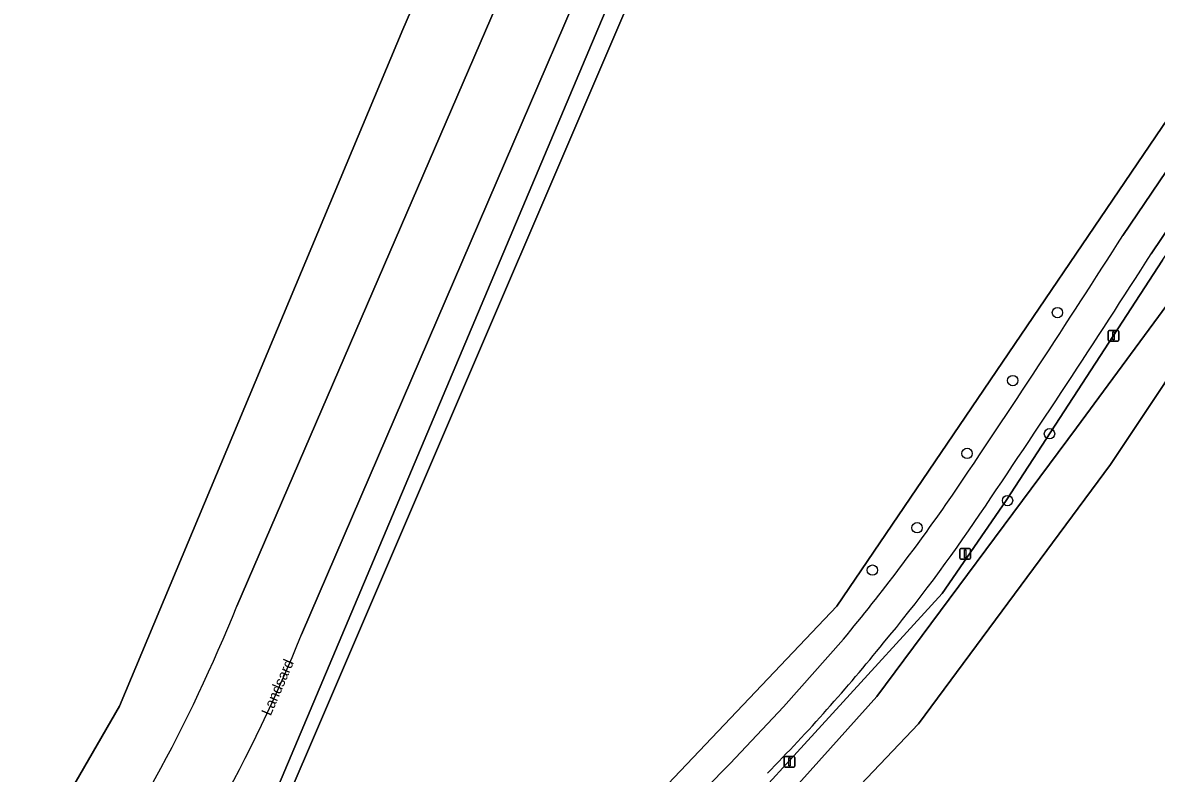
# Model space of a CAD drawing. Extents: x 155209 to 156748, y 385356 to 388487.
# Drawn here: x 155855.7 to 155962.6, y 385866.9 to 385937.7 of the extents above; entities that cross this region are included whole.
import ezdxf

# ---------------------------------------------------------------- set-up
doc = ezdxf.new("R2010")
doc.units = 0
for name, color, linetype in [('IMGEO_Berm_groen', 7, 'Continuous'), ('IMGEO_Boom', 7, 'Continuous'), ('IMGEO_Fietspad_gesloten', 7, 'Continuous'), ('IMGEO_Gemengd_bos', 7, 'Continuous'), ('IMGEO_Groenvoorziening', 7, 'Continuous'), ('IMGEO_Lichtmast', 7, 'Continuous'), ('IMGEO_Meer_plas_ven_vijver', 7, 'Continuous'), ('IMGEO_Naaldbos', 7, 'Continuous'), ('IMGEO_Oever', 7, 'Continuous'), ('IMGEO_Openbare_ruimte_label', 7, 'Continuous'), ('IMGEO_Rijbaan_lokaal_gesloten', 7, 'Continuous'), ('IMGEO_Waterloop', 7, 'Continuous')]:
    doc.layers.add(name, color=color, linetype=linetype)

msp = doc.modelspace()

# ---------------------------------------------------------------- linework, layer by layer
at = {"layer": 'IMGEO_Berm_groen'}
for points in [[(155908.98, 385959.23), (155905.66, 385960.64), (155915.24, 385982.82), (155916.17, 385982.42), (155916.98, 385984.34), (155917.62, 385985.86), (155917.92, 385986.55), (155913.79, 385988.33), (155913.52, 385987.69), (155912.88, 385986.21), (155891.58, 385937.04), (155864.83, 385873.2), (155853.13, 385852.94), (155810.49, 385814.26), (155804.37, 385808.7), (155774.12, 385781.08), (155771.15, 385778.38), (155769.03, 385773.41), (155767.97, 385771.34), (155768.61, 385770.6), (155770.85, 385768.09), (155773.86, 385770.85), (155810.94, 385803.67), (155837.84, 385827.57)], [(155875.91, 385882.64), (155908.98, 385959.23)], [(155959.49, 385917.6), (155967.71, 385929.79), (155976.74, 385943.04), (155976.86, 385943.15), (155976.15, 385944.26), (155974.75, 385944.88), (155932.5, 385882.64), (155851.64, 385797.46), (155851.5, 385797.12)], [(155921.77, 385861.19), (155942.45, 385883.84), (155948.49, 385892.6), (155963.23, 385915.28), (155979.15, 385938.71), (155979.16, 385939.55), (155978.86, 385940.02), (155970.6, 385928.4), (155962.17, 385915.88)], [(155887.11, 385831.96), (155922.46, 385867.78), (155927.49, 385873.15), (155933.14, 385879.54)]]:
    msp.add_lwpolyline(points, dxfattribs=at)
for centre, radius, start, end in [((155057.31, 386492.1), 1069.56, 325.94143, 327.51135), ((155056.98, 386494.04), 1074.07, 325.8648, 327.43296), ((155776.14, 386009.1), 203.56, 320.4704, 325.2588), ((155816.96, 385978.33), 155.64, 320.4219, 326.0119), ((155732.32, 385940.67), 154.88, 324.673, 337.9939), ((155802.68, 385987.72), 172.63, 315.5693, 321.0394)]:
    msp.add_arc(centre, radius, start, end, dxfattribs=at)
at = {"layer": 'IMGEO_Boom'}
for centre in [(155953.32, 385910.33), (155949.1, 385903.92), (155952.57, 385898.91), (155944.79, 385897.05), (155948.61, 385892.6), (155940.08, 385890.04), (155935.86, 385886.04)]:
    msp.add_circle(centre, 0.489, dxfattribs=at)
at = {"layer": 'IMGEO_Fietspad_gesloten'}
for points in [[(155962.17, 385915.88), (155970.6, 385928.4), (155978.86, 385940.02), (155979.13, 385940.39), (155976.97, 385943.25), (155976.86, 385943.15), (155976.74, 385943.04), (155967.71, 385929.79), (155959.49, 385917.6)], [(155933.14, 385879.54), (155927.49, 385873.15), (155922.46, 385867.78), (155887.11, 385831.96)]]:
    msp.add_lwpolyline(points, dxfattribs=at)
for centre, radius, start, end in [((155057.31, 386492.1), 1069.56, 325.94143, 327.51135), ((155056.98, 386494.04), 1074.07, 325.8648, 327.43296), ((155776.14, 386009.1), 203.56, 320.4704, 325.2588), ((155816.96, 385978.33), 155.64, 320.4219, 326.0119), ((155802.68, 385987.72), 172.63, 315.5693, 321.0394)]:
    msp.add_arc(centre, radius, start, end, dxfattribs=at)
at = {"layer": 'IMGEO_Gemengd_bos'}
msp.add_lwpolyline([(155872.65, 386005.2), (155867.03, 385991.83), (155868.12, 385991.46), (155859.4, 385970.5), (155853.12, 385955.51), (155833.54, 385909.24), (155796.45, 385820.47), (155810.49, 385814.26), (155853.13, 385852.94), (155864.83, 385873.2), (155891.58, 385937.04), (155912.88, 385986.21)], dxfattribs=at)
at = {"layer": 'IMGEO_Groenvoorziening'}
for points in [[(155783.19, 385764.8), (155786.45, 385768.76), (155814.49, 385793.57), (155841.44, 385817.51), (155847.37, 385823.23), (155851.61, 385826.93), (155858.57, 385833.47), (155863.57, 385838.09), (155867.53, 385841.42), (155870.87, 385844.48), (155910.3, 385937.91), (155931.88, 385987.98), (155929.14, 385989.38), (155882.02, 385879.97)], [(155963.23, 385915.28), (155948.49, 385892.6), (155942.45, 385883.84), (155921.77, 385861.19), (155901.12, 385837.98), (155877.21, 385813.21), (155877.16, 385813.41), (155877.27, 385813.85), (155877.54, 385814.49), (155878.1, 385815.73), (155878.45, 385816.54), (155878.76, 385817.29), (155879.14, 385818.21)]]:
    msp.add_lwpolyline(points, dxfattribs=at)
msp.add_lwpolyline([(155888.26, 385819.77), (155912.24, 385847.3), (155936.28, 385874.13), (155955.11, 385899.46), (155977.8, 385930.25), (155991.84, 385915.75), (156009.13, 385895.28), (156010.24, 385891.85), (156007.09, 385887), (155994.39, 385870.49), (155981.86, 385856.22), (155967.56, 385842.81), (155949.65, 385831.93), (155932.36, 385825.07), (155911.29, 385820.8), (155889.32, 385814.55)], close=True, dxfattribs=at)
msp.add_arc((155731.43, 385941.36), 162.62, 324.6652, 337.8195, dxfattribs=at)
at = {"layer": 'IMGEO_Lichtmast'}
for p, q in [((155958.21, 385908.65), (155959, 385908.65)), ((155959, 385908.65), (155958.21, 385908.65)), ((155958.11, 385907.75), (155958.11, 385908.55)), ((155958.11, 385908.55), (155958.11, 385907.75)), ((155959, 385907.65), (155958.21, 385907.65)), ((155958.21, 385907.65), (155959, 385907.65)), ((155959.1, 385908.55), (155959.1, 385907.75)), ((155959.1, 385907.75), (155959.1, 385908.55)), ((155944.12, 385887.17), (155944.12, 385887.97)), ((155944.12, 385887.97), (155944.12, 385887.17)), ((155944.22, 385888.07), (155945.01, 385888.07)), ((155945.01, 385888.07), (155944.22, 385888.07)), ((155945.11, 385887.97), (155945.11, 385887.17)), ((155945.11, 385887.17), (155945.11, 385887.97)), ((155945.01, 385887.07), (155944.22, 385887.07)), ((155944.22, 385887.07), (155945.01, 385887.07)), ((155927.55, 385867.55), (155927.55, 385868.35)), ((155927.55, 385868.35), (155927.55, 385867.55)), ((155927.65, 385868.45), (155928.44, 385868.45)), ((155928.44, 385868.45), (155927.65, 385868.45)), ((155928.54, 385868.35), (155928.54, 385867.55)), ((155928.54, 385867.55), (155928.54, 385868.35)), ((155928.44, 385867.45), (155927.65, 385867.45)), ((155927.65, 385867.45), (155928.44, 385867.45))]:
    msp.add_line(p, q, dxfattribs=at)
for points in [[(155958.53, 385908.53), (155958.68, 385908.53), (155958.68, 385907.78), (155958.53, 385907.78), (155958.53, 385908.53)], [(155944.54, 385887.94), (155944.69, 385887.94), (155944.69, 385887.19), (155944.54, 385887.19), (155944.54, 385887.94)], [(155927.97, 385868.32), (155928.12, 385868.32), (155928.12, 385867.57), (155927.97, 385867.57), (155927.97, 385868.32)]]:
    msp.add_lwpolyline(points, dxfattribs=at)
for centre, start, end in [((155958.21, 385908.55), 90, 180), ((155958.21, 385908.55), 90, 180), ((155959, 385908.55), 0, 90), ((155959, 385908.55), 360, 90), ((155958.21, 385907.75), 180, 270), ((155958.21, 385907.75), 180, 270), ((155959, 385907.75), 270, 0), ((155959, 385907.75), 270, 0), ((155944.22, 385887.97), 90, 180), ((155944.22, 385887.97), 90, 180), ((155945.01, 385887.97), 0, 90), ((155945.01, 385887.97), 360, 90), ((155944.22, 385887.17), 180, 270), ((155944.22, 385887.17), 180, 270), ((155945.01, 385887.17), 270, 0), ((155945.01, 385887.17), 270, 0), ((155927.65, 385868.35), 90, 180), ((155927.65, 385868.35), 90, 180), ((155928.44, 385868.35), 0, 90), ((155928.44, 385868.35), 360, 90), ((155927.65, 385867.55), 180, 270), ((155927.65, 385867.55), 180, 270), ((155928.44, 385867.55), 270, 0), ((155928.44, 385867.55), 270, 0)]:
    msp.add_arc(centre, 0.1, start, end, dxfattribs=at)
at = {"layer": 'IMGEO_Meer_plas_ven_vijver'}
msp.add_lwpolyline([(155889.54, 385819.58), (155889.68, 385816.12), (155910.83, 385824.07), (155930.33, 385829.81), (155946.96, 385837.15), (155963.61, 385846.6), (155978.46, 385860.05), (155988.82, 385873.26), (156004.4, 385893.66), (155989.29, 385913.13), (155978.69, 385926.6), (155958.32, 385896), (155940.2, 385871.53), (155915.28, 385845.31), (155893.83, 385822.92)], close=True, dxfattribs=at)
at = {"layer": 'IMGEO_Naaldbos'}
msp.add_lwpolyline([(155974.75, 385944.88), (155969.49, 385947.2), (155967.94, 385952.96), (155961.9, 385955.8), (155959.69, 385962.26), (155956.09, 385964.8), (155955.77, 385969.98), (155948.24, 385973.41), (155946.55, 385980.5), (155933.29, 385987.26), (155871.9, 385843.96), (155870.19, 385841.27), (155853.47, 385801.77), (155851.64, 385797.46), (155932.5, 385882.64)], close=True, dxfattribs=at)
at = {"layer": 'IMGEO_Oever'}
for points in [[(155888.26, 385819.77), (155889.32, 385814.55), (155911.29, 385820.8), (155932.36, 385825.07), (155949.65, 385831.93), (155967.56, 385842.81), (155981.86, 385856.22), (155994.39, 385870.49), (156007.09, 385887), (156010.24, 385891.85), (156009.13, 385895.28), (155991.84, 385915.75), (155977.8, 385930.25), (155955.11, 385899.46), (155936.28, 385874.13), (155912.24, 385847.3)], [(155889.54, 385819.58), (155893.83, 385822.92), (155915.28, 385845.31), (155940.2, 385871.53), (155958.32, 385896), (155978.69, 385926.6), (155989.29, 385913.13), (156004.4, 385893.66), (155988.82, 385873.26), (155978.46, 385860.05), (155963.61, 385846.6), (155946.96, 385837.15), (155930.33, 385829.81), (155910.83, 385824.07), (155889.68, 385816.12)]]:
    msp.add_lwpolyline(points, close=True, dxfattribs=at)
at = {"layer": 'IMGEO_Rijbaan_lokaal_gesloten'}
for points in [[(155944.24, 386024.53), (155949.14, 386035.92), (155965.64, 386074.34), (155984.91, 386119.23), (156009.58, 386176.82), (156003.54, 386179.53), (155989.7, 386147.22), (155959.53, 386076.88), (155927.74, 386002.82), (155923, 385991.79), (155918.96, 385982.46), (155913.39, 385969.48), (155908.98, 385959.23), (155875.91, 385882.64)], [(155882.02, 385879.97), (155929.14, 385989.38), (155934.02, 386000.73), (155944.24, 386024.53)]]:
    msp.add_lwpolyline(points, dxfattribs=at)
for centre, radius, start, end in [((155732.32, 385940.67), 154.88, 324.673, 337.9939), ((155731.43, 385941.36), 162.62, 324.6652, 337.8195)]:
    msp.add_arc(centre, radius, start, end, dxfattribs=at)
at = {"layer": 'IMGEO_Waterloop'}
for points in [[(155933.29, 385987.26), (155931.88, 385987.98), (155910.3, 385937.91), (155870.87, 385844.48)], [(155871.9, 385843.96), (155933.29, 385987.26)]]:
    msp.add_lwpolyline(points, dxfattribs=at)

# ---------------------------------------------------------------- texts
at = {"layer": 'IMGEO_Openbare_ruimte_label'}
msp.add_text('Landsard', height=1, rotation=66.6134, dxfattribs=at).set_placement((155879.1, 385872.23))

doc.saveas('drawing.dxf')
